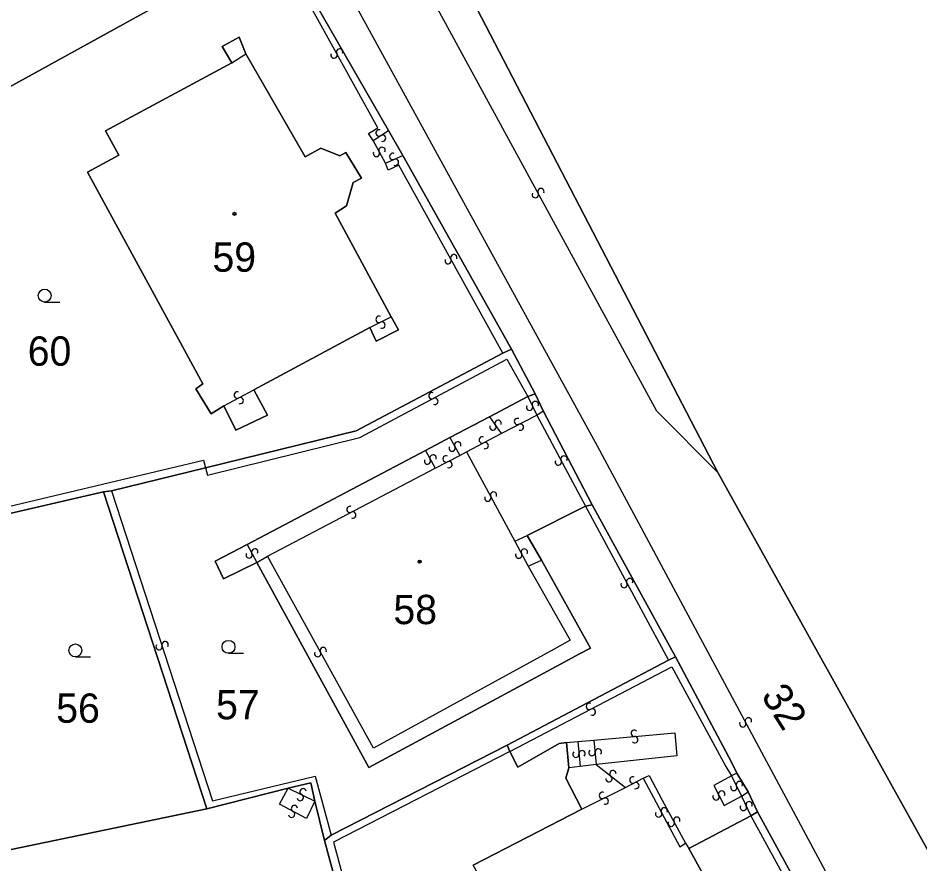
# Model space of a CAD drawing. Extents: x -600309 to -598967, y -1161267 to -1160292.
# Drawn here: x -599061.3 to -599009, y -1160829.7 to -1160780.7 of the extents above; entities that cross this region are included whole.
import ezdxf

# ---------------------------------------------------------------- set-up
doc = ezdxf.new("R2010")
doc.units = 0
for name, color, linetype in [('Level 1', 7, 'Continuous'), ('Level 13', 7, 'Continuous'), ('Level 3', 7, 'Continuous'), ('Level 4', 7, 'Continuous'), ('Level 5', 7, 'Continuous'), ('Level 57', 7, 'Continuous'), ('Level 60', 7, 'Continuous'), ('Vrstva 60', 7, 'Continuous')]:
    doc.layers.add(name, color=color, linetype=linetype)

msp = doc.modelspace()

# ---------------------------------------------------------------- linework, layer by layer
at = {"layer": 'Level 1'}
for points in [[(-598967.108, -1160884.839), (-598972.51, -1160879.73), (-598974.58, -1160878.03), (-598979.64, -1160873.91), (-598989.61, -1160863.67), (-598991.16, -1160861.71), (-599008.15, -1160829.7), (-599020.75, -1160807.03), (-599038.86, -1160772.13)], [(-599038.86, -1160772.13), (-599020.75, -1160807.03)], [(-599050.09, -1160778.17), (-599066.98, -1160787.5)], [(-599039.85, -1160787.18), (-599044.94, -1160778.29)], [(-599048.93, -1160783.27), (-599049.48, -1160782.31), (-599048.51, -1160781.78), (-599048.11, -1160782.75)], [(-599048.93, -1160783.27), (-599056.25, -1160787.2), (-599055.48, -1160788.62), (-599057.3, -1160789.6), (-599050.6, -1160801.88), (-599051.02, -1160802.17), (-599050.13, -1160803.62), (-599049.4, -1160803.16)], [(-599048.11, -1160782.75), (-599044.67, -1160788.71), (-599043.77, -1160788.21), (-599042.67, -1160788.66), (-599042.31, -1160788.46), (-599041.41, -1160789.96), (-599041.9, -1160790.21), (-599042.27, -1160791.56), (-599042.94, -1160791.99), (-599039.69, -1160797.99)], [(-599039.02, -1160788.63), (-599039.85, -1160787.18)], [(-599032.71, -1160799.87), (-599039.02, -1160788.63)], [(-599039.69, -1160797.99), (-599039.26, -1160798.75), (-599040.56, -1160799.41), (-599040.92, -1160798.62)], [(-599040.92, -1160798.62), (-599047.66, -1160802.23)], [(-599033.21, -1160800.1), (-599032.71, -1160799.87)], [(-599031.34, -1160802.47), (-599032.71, -1160799.87)], [(-599050.45, -1160806.76), (-599041.71, -1160804.6), (-599033.21, -1160800.1)], [(-599047.66, -1160802.23), (-599046.86, -1160803.69), (-599048.7, -1160804.57), (-599049.4, -1160803.16)], [(-599031.34, -1160802.47), (-599031.76, -1160802.62)], [(-599030.88, -1160803.45), (-599031.34, -1160802.47)], [(-599031.76, -1160802.62), (-599033.98, -1160803.79)], [(-599028.03, -1160808.9), (-599030.88, -1160803.45)], [(-599033.98, -1160803.79), (-599036.28, -1160805)], [(-599036.28, -1160805), (-599037.7, -1160805.75)], [(-599037.7, -1160805.75), (-599048.04, -1160811.2)], [(-599055.9, -1160808.08), (-599050.45, -1160806.76)], [(-599020.75, -1160807.03), (-599008.15, -1160829.7)], [(-599062.75, -1160809.62), (-599056.36, -1160808.14)], [(-599056.36, -1160808.14), (-599055.9, -1160808.08)], [(-599056.36, -1160808.14), (-599050.37, -1160826.54)], [(-599031.8, -1160810.67), (-599028.42, -1160808.97)], [(-599028.42, -1160808.97), (-599028.03, -1160808.9)], [(-599023.21, -1160817.72), (-599028.03, -1160808.9)], [(-599030.97, -1160812.1), (-599031.8, -1160810.67)], [(-599048.04, -1160811.2), (-599049.89, -1160812.16), (-599049.41, -1160813.2), (-599047.48, -1160812.24)], [(-599047.48, -1160812.24), (-599040.98, -1160824.14), (-599029.87, -1160818.14), (-599028.76, -1160817.55), (-599028.14, -1160817.21), (-599030.97, -1160812.1)], [(-599023.61, -1160817.9), (-599023.21, -1160817.72)], [(-599019.64, -1160824.46), (-599019.95, -1160823.82), (-599023.21, -1160817.72)], [(-599032.96, -1160822.84), (-599023.61, -1160817.9)], [(-599043.16, -1160828.06), (-599032.96, -1160822.84)], [(-599032.81, -1160823.21), (-599032.96, -1160822.84)], [(-599029.52, -1160822.68), (-599029.95, -1160822.75), (-599032.35, -1160824.12), (-599032.81, -1160823.21)], [(-599029.39, -1160824.15), (-599029.52, -1160822.68)], [(-599028.63, -1160826.55), (-599029.57, -1160824.76), (-599029.39, -1160824.15)], [(-599019, -1160825.54), (-599019.64, -1160824.46)], [(-599045.66, -1160825.34), (-599044.34, -1160825.02), (-599044.11, -1160826.08)], [(-599050.37, -1160826.54), (-599045.66, -1160825.34)], [(-599018.45, -1160826.7), (-599019, -1160825.54)], [(-599043.55, -1160828.36), (-599044.11, -1160826.08)], [(-599063.7, -1160829.3), (-599050.37, -1160826.54)], [(-599022.44, -1160828.84), (-599019.86, -1160833.47), (-599029.89, -1160838.75), (-599031.09, -1160838.89), (-599032.45, -1160838.52), (-599033.26, -1160837.58), (-599033.82, -1160836.06), (-599033.56, -1160834.59), (-599032.78, -1160833.61), (-599034.94, -1160829.79), (-599028.63, -1160826.55)], [(-599018.84, -1160826.94), (-599022.44, -1160828.84)], [(-599018.45, -1160826.7), (-599018.84, -1160826.94)], [(-599012.17, -1160838.2), (-599018.45, -1160826.7)], [(-599043.55, -1160828.36), (-599043.16, -1160828.06)], [(-599038.63, -1160846.55), (-599043.55, -1160828.36)]]:
    msp.add_lwpolyline(points, dxfattribs=at)
at = {"layer": 'Level 13'}
for centre, start, end in [((-599043.002, -1160782.808), 156.2751, 28.3731), ((-599042.678, -1160782.632), 336.0606, 208.6506), ((-599040.39, -1160787.325), 70.914, 303.012), ((-599040.189, -1160787.634), 250.6995, 123.2895), ((-599040.543, -1160788.517), 155.9832, 28.0812), ((-599040.218, -1160788.343), 335.7687, 208.3587), ((-599039.596, -1160788.692), 62.0752, 294.1732), ((-599039.444, -1160789.028), 241.8607, 114.4507), ((-599031.008, -1160790.733), 335.6989, 208.2889), ((-599031.333, -1160790.907), 155.9133, 28.0113), ((-599036.382, -1160794.738), 156.3246, 28.4226), ((-599036.059, -1160794.562), 336.1101, 208.7001), ((-599040.393, -1160798.145), 64.494, 296.592), ((-599040.227, -1160798.474), 244.2796, 116.8696), ((-599048.615, -1160802.527), 65.4965, 297.5945), ((-599037.325, -1160802.566), 65.4487, 297.5467), ((-599048.444, -1160802.853), 245.282, 117.872), ((-599037.154, -1160802.893), 245.2343, 117.8243), ((-599031.333, -1160803.081), 333.2916, 205.3896), ((-599031.666, -1160803.24), 153.0772, 25.6672), ((-599033.487, -1160804.177), 341.7321, 213.8301), ((-599032.364, -1160804.066), 64.9255, 297.0235), ((-599033.792, -1160804.383), 161.5177, 34.1077), ((-599032.196, -1160804.394), 244.7111, 117.3011), ((-599034.405, -1160805.136), 65.1782, 297.2762), ((-599036.151, -1160805.61), 156.5424, 29.1324), ((-599035.828, -1160805.431), 336.7569, 208.8549), ((-599034.235, -1160805.463), 244.9638, 117.5538), ((-599037.581, -1160806.358), 156.1183, 28.7083), ((-599037.258, -1160806.182), 336.3328, 208.4308), ((-599036.504, -1160806.236), 65.0486, 297.1466), ((-599029.667, -1160806.245), 335.479, 207.577), ((-599036.335, -1160806.563), 244.8342, 117.4242), ((-599029.993, -1160806.416), 155.2645, 27.8545), ((-599033.757, -1160808.334), 335.8121, 207.9101), ((-599034.082, -1160808.507), 155.5976, 28.1876), ((-599042.084, -1160809.166), 65.0341, 297.1321), ((-599041.915, -1160809.493), 244.8197, 117.4097), ((-599047.597, -1160811.634), 335.6735, 207.7715), ((-599031.967, -1160811.645), 335.4859, 207.5839), ((-599047.922, -1160811.807), 155.459, 28.049), ((-599032.293, -1160811.816), 155.2715, 27.8615), ((-599026.182, -1160813.527), 155.4667, 28.0567), ((-599025.857, -1160813.354), 335.6811, 207.7791), ((-599053.145, -1160817.126), 145.21, 17.8), ((-599052.794, -1160817.014), 325.4244, 197.5224), ((-599043.628, -1160817.352), 336.0421, 208.6321), ((-599043.952, -1160817.528), 156.2566, 28.3546), ((-599028.194, -1160820.586), 64.9526, 297.0506), ((-599028.026, -1160820.914), 244.7382, 117.3282), ((-599018.977, -1160821.434), 335.5647, 207.6627), ((-599019.303, -1160821.606), 155.3503, 27.9403), ((-599025.594, -1160822.156), 42.3688, 274.4668), ((-599025.565, -1160822.523), 222.1544, 94.7444), ((-599028.983, -1160823.366), 132.2465, 4.8365), ((-599028.616, -1160823.335), 312.461, 184.559), ((-599028.043, -1160823.266), 132.3527, 4.9427), ((-599027.676, -1160823.235), 312.5672, 184.6652), ((-599026.835, -1160824.496), 359.3348, 231.4328), ((-599027.064, -1160824.784), 179.1203, 51.7103), ((-599025.676, -1160824.857), 65.707, 297.805), ((-599025.503, -1160825.182), 245.4925, 118.0825), ((-599019.494, -1160825.129), 333.9378, 206.0358), ((-599044.799, -1160825.544), 11.852, 243.95), ((-599027.44, -1160825.754), 63.6654, 295.7634), ((-599020.525, -1160825.678), 334.3316, 206.4296), ((-599019.825, -1160825.292), 153.7233, 26.3133), ((-599044.96, -1160825.876), 191.6376, 64.2276), ((-599027.279, -1160826.085), 243.4509, 116.0409), ((-599020.854, -1160825.843), 154.1171, 26.7071), ((-599018.932, -1160826.294), 332.307, 204.405), ((-599045.294, -1160826.517), 9.4446, 242.0346), ((-599023.857, -1160826.654), 335.5274, 207.6253), ((-599019.267, -1160826.447), 152.0926, 24.6826), ((-599045.467, -1160826.842), 189.659, 61.757), ((-599024.183, -1160826.826), 155.3129, 27.9029), ((-599023.127, -1160827.194), 335.7418, 207.8398), ((-599023.452, -1160827.367), 155.5273, 28.1173)]:
    msp.add_arc(centre, 0.184, start, end, dxfattribs=at)
at = {"layer": 'Level 3'}
for points in [[(-599020.75, -1160807.03), (-599024.29, -1160803.47), (-599038.05, -1160778.17), (-599040.52, -1160772.93)], [(-599044.45, -1160775.03), (-599042.71, -1160778.18), (-599027.74, -1160805.48), (-599010.55, -1160837.55), (-598995.06, -1160866.56), (-598990.88, -1160872.86), (-598987.65, -1160876.63), (-598967.63, -1160897.91), (-598967.108, -1160898.408)], [(-599040.74, -1160787.77), (-599041.01, -1160787.36), (-599040.46, -1160787.04), (-599045.23, -1160778.4)], [(-599048.93, -1160783.27), (-599048.11, -1160782.75)], [(-599040.74, -1160787.77), (-599039.85, -1160787.18)], [(-599066.98, -1160787.5), (-599062.28, -1160809.1), (-599050.56, -1160806.31), (-599050.45, -1160806.76)], [(-599040.02, -1160789.09), (-599040.74, -1160787.77)], [(-599040.02, -1160789.09), (-599039.02, -1160788.63)], [(-599033.21, -1160800.1), (-599039.24, -1160789.2), (-599039.87, -1160789.48), (-599040.02, -1160789.09)], [(-599040.92, -1160798.62), (-599039.69, -1160797.99)], [(-599050.45, -1160806.76), (-599050.33, -1160807.18), (-599041.51, -1160805), (-599032.98, -1160800.45), (-599031.76, -1160802.62)], [(-599049.4, -1160803.16), (-599047.66, -1160802.23)], [(-599031.76, -1160802.62), (-599031.24, -1160803.69)], [(-599031.24, -1160803.69), (-599030.88, -1160803.45)], [(-599033.98, -1160803.79), (-599033.31, -1160804.77)], [(-599033.31, -1160804.77), (-599031.24, -1160803.69)], [(-599031.24, -1160803.69), (-599028.42, -1160808.97)], [(-599036.28, -1160805), (-599035.7, -1160806.03)], [(-599035.32, -1160805.83), (-599033.31, -1160804.77)], [(-599037.7, -1160805.75), (-599037.13, -1160806.78)], [(-599037.13, -1160806.78), (-599035.7, -1160806.03)], [(-599035.7, -1160806.03), (-599035.32, -1160805.83)], [(-599035.32, -1160805.83), (-599032.52, -1160811)], [(-599046.86, -1160811.88), (-599037.13, -1160806.78)], [(-599055.9, -1160808.08), (-599050.04, -1160826.06), (-599044.1, -1160824.63), (-599043.16, -1160828.06)], [(-599028.42, -1160808.97), (-599023.61, -1160817.9)], [(-599032.52, -1160811), (-599031.8, -1160810.67)], [(-599048.04, -1160811.2), (-599047.48, -1160812.24)], [(-599032.52, -1160811), (-599031.74, -1160812.46)], [(-599047.48, -1160812.24), (-599046.86, -1160811.88)], [(-599031.74, -1160812.46), (-599029.32, -1160816.74), (-599030.23, -1160817.27), (-599040.72, -1160823.01), (-599046.86, -1160811.88)], [(-599031.74, -1160812.46), (-599030.97, -1160812.1)], [(-599032.81, -1160823.21), (-599023.41, -1160818.3), (-599020.29, -1160824.07), (-599019.96, -1160824.62)], [(-599027.93, -1160822.54), (-599023.24, -1160822.13), (-599023.13, -1160823.45), (-599027.8, -1160823.97)], [(-599029.52, -1160822.68), (-599028.87, -1160822.62)], [(-599028.87, -1160822.62), (-599027.93, -1160822.54)], [(-599028.87, -1160822.62), (-599028.74, -1160824.08)], [(-599027.93, -1160822.54), (-599027.8, -1160823.97)], [(-599032.81, -1160823.21), (-599043.03, -1160828.47), (-599038.17, -1160846.39)], [(-599027.8, -1160823.97), (-599028.74, -1160824.08)], [(-599027.8, -1160823.97), (-599026.1, -1160825.3)], [(-599028.74, -1160824.08), (-599029.39, -1160824.15)], [(-599019.64, -1160824.46), (-599019.96, -1160824.62)], [(-599026.1, -1160825.3), (-599025.08, -1160824.75)], [(-599025.08, -1160824.75), (-599024.73, -1160824.59), (-599023.97, -1160826.03), (-599022.62, -1160828.53)], [(-599025.08, -1160824.75), (-599022.95, -1160828.73), (-599022.62, -1160828.53)], [(-599019.96, -1160824.62), (-599020.98, -1160825.18), (-599020.39, -1160826.34), (-599019.37, -1160825.8)], [(-599019.96, -1160824.62), (-599019.37, -1160825.8)], [(-599044.11, -1160826.08), (-599044.59, -1160827.1), (-599046.17, -1160826.27), (-599045.66, -1160825.34)], [(-599045.66, -1160825.34), (-599044.11, -1160826.08)], [(-599028.63, -1160826.55), (-599026.1, -1160825.3)], [(-599019.37, -1160825.8), (-599019, -1160825.54)], [(-599019.37, -1160825.8), (-599018.84, -1160826.94)], [(-599018.84, -1160826.94), (-599012.62, -1160838.33)], [(-599022.62, -1160828.53), (-599022.44, -1160828.84)]]:
    msp.add_lwpolyline(points, dxfattribs=at)
at = {"layer": 'Level 5'}
for p, q in [((-599059.78, -1160797.14), (-599058.905, -1160797.14)), ((-599058, -1160817.72), (-599057.125, -1160817.72)), ((-599049.12, -1160817.51), (-599048.245, -1160817.51))]:
    msp.add_line(p, q, dxfattribs=at)
for centre, radius in [((-599048.77, -1160792.02), 0.09), ((-599048.77, -1160792.02), 0.0521), ((-599059.78, -1160796.765), 0.375), ((-599038.04, -1160812.2), 0.09), ((-599038.04, -1160812.2), 0.0521), ((-599058, -1160817.345), 0.375), ((-599049.12, -1160817.135), 0.375)]:
    msp.add_circle(centre, radius, dxfattribs=at)
at = {"layer": 'Level 60'}
for points in [[(-599074.8, -1160633.37), (-599072.29, -1160646.3), (-599071.63, -1160649.97), (-599069.19, -1160662.47), (-599062.42, -1160697.34), (-599058.05, -1160720.03), (-599057.39, -1160723.33), (-599052.68, -1160747.38), (-599049.58, -1160762.75), (-599048.05, -1160769.81), (-599046.8, -1160774.69), (-599046.22, -1160775.87), (-599050.09, -1160778.17), (-599066.98, -1160787.5), (-599067.47, -1160787.83), (-599068.04, -1160784.69), (-599078.87, -1160791.24), (-599085.73, -1160791.88), (-599086.32, -1160791.93), (-599104.44, -1160657.19), (-599104.72, -1160655.07), (-599117.85, -1160556.94)], [(-599034.94, -1160829.79), (-599028.63, -1160826.55), (-599029.57, -1160824.76), (-599029.39, -1160824.15), (-599029.52, -1160822.68), (-599029.95, -1160822.75), (-599032.35, -1160824.12), (-599032.81, -1160823.21), (-599032.96, -1160822.84), (-599023.61, -1160817.9), (-599023.21, -1160817.72), (-599019.95, -1160823.82), (-599019.64, -1160824.46), (-599019, -1160825.54), (-599018.45, -1160826.7), (-599018.84, -1160826.94), (-599022.44, -1160828.84), (-599019.86, -1160833.47)], [(-599038.63, -1160846.55), (-599043.55, -1160828.36), (-599043.16, -1160828.06), (-599032.96, -1160822.84), (-599032.81, -1160823.21), (-599032.35, -1160824.12), (-599029.95, -1160822.75), (-599029.52, -1160822.68), (-599029.39, -1160824.15), (-599029.57, -1160824.76), (-599028.63, -1160826.55), (-599034.94, -1160829.79)], [(-599019.86, -1160833.47), (-599022.44, -1160828.84), (-599018.84, -1160826.94), (-599018.45, -1160826.7), (-599012.17, -1160838.2)]]:
    msp.add_lwpolyline(points, dxfattribs=at)
for points in [[(-599050.09, -1160778.17), (-599046.22, -1160775.87), (-599044.94, -1160778.29), (-599039.85, -1160787.18), (-599039.02, -1160788.63), (-599032.71, -1160799.87), (-599033.21, -1160800.1), (-599041.71, -1160804.6), (-599050.45, -1160806.76), (-599055.9, -1160808.08), (-599056.36, -1160808.14), (-599062.75, -1160809.62), (-599065.44, -1160796.64), (-599065.56, -1160796.09), (-599067.47, -1160787.83), (-599066.98, -1160787.5)], [(-599056.25, -1160787.2), (-599048.93, -1160783.27), (-599049.48, -1160782.31), (-599048.51, -1160781.78), (-599048.11, -1160782.75), (-599044.67, -1160788.71), (-599043.77, -1160788.21), (-599042.67, -1160788.66), (-599042.31, -1160788.46), (-599041.41, -1160789.96), (-599041.9, -1160790.21), (-599042.27, -1160791.56), (-599042.94, -1160791.99), (-599039.69, -1160797.99), (-599039.26, -1160798.75), (-599040.56, -1160799.41), (-599040.92, -1160798.62), (-599047.66, -1160802.23), (-599046.86, -1160803.69), (-599048.7, -1160804.57), (-599049.4, -1160803.16), (-599050.13, -1160803.62), (-599051.02, -1160802.17), (-599050.6, -1160801.88), (-599057.3, -1160789.6), (-599055.48, -1160788.62)], [(-599048.93, -1160783.27), (-599056.25, -1160787.2), (-599055.48, -1160788.62), (-599057.3, -1160789.6), (-599050.6, -1160801.88), (-599051.02, -1160802.17), (-599050.13, -1160803.62), (-599049.4, -1160803.16), (-599048.7, -1160804.57), (-599046.86, -1160803.69), (-599047.66, -1160802.23), (-599040.92, -1160798.62), (-599040.56, -1160799.41), (-599039.26, -1160798.75), (-599039.69, -1160797.99), (-599042.94, -1160791.99), (-599042.27, -1160791.56), (-599041.9, -1160790.21), (-599041.41, -1160789.96), (-599042.31, -1160788.46), (-599042.67, -1160788.66), (-599043.77, -1160788.21), (-599044.67, -1160788.71), (-599048.11, -1160782.75), (-599048.51, -1160781.78), (-599049.48, -1160782.31)], [(-599028.03, -1160808.9), (-599023.21, -1160817.72), (-599023.61, -1160817.9), (-599032.96, -1160822.84), (-599043.16, -1160828.06), (-599043.55, -1160828.36), (-599044.11, -1160826.08), (-599044.34, -1160825.02), (-599045.66, -1160825.34), (-599050.37, -1160826.54), (-599056.36, -1160808.14), (-599055.9, -1160808.08), (-599050.45, -1160806.76), (-599041.71, -1160804.6), (-599033.21, -1160800.1), (-599032.71, -1160799.87), (-599031.34, -1160802.47), (-599031.76, -1160802.62), (-599033.98, -1160803.79), (-599036.28, -1160805), (-599037.7, -1160805.75), (-599048.04, -1160811.2), (-599049.89, -1160812.16), (-599049.41, -1160813.2), (-599047.48, -1160812.24), (-599040.98, -1160824.14), (-599029.87, -1160818.14), (-599028.76, -1160817.55), (-599028.14, -1160817.21), (-599030.97, -1160812.1), (-599031.8, -1160810.67), (-599028.42, -1160808.97)], [(-599030.88, -1160803.45), (-599028.03, -1160808.9), (-599028.42, -1160808.97), (-599031.8, -1160810.67), (-599030.97, -1160812.1), (-599028.14, -1160817.21), (-599028.76, -1160817.55), (-599029.87, -1160818.14), (-599040.98, -1160824.14), (-599047.48, -1160812.24), (-599049.41, -1160813.2), (-599049.89, -1160812.16), (-599048.04, -1160811.2), (-599037.7, -1160805.75), (-599036.28, -1160805), (-599033.98, -1160803.79), (-599031.76, -1160802.62), (-599031.34, -1160802.47)], [(-599050.37, -1160826.54), (-599063.7, -1160829.3), (-599064.19, -1160829.27), (-599064.53, -1160821.61), (-599064.36, -1160821.58), (-599062.63, -1160821.32), (-599062.9, -1160819.83), (-599063.43, -1160816.76), (-599065.98, -1160816.96), (-599066.49, -1160812.26), (-599066.65, -1160810.49), (-599062.75, -1160809.62), (-599056.36, -1160808.14)], [(-599056.09, -1160847.43), (-599062.58, -1160847.78), (-599062.95, -1160841.27), (-599063.32, -1160841.25), (-599063.63, -1160837.22), (-599063.2, -1160837.18), (-599063.7, -1160829.3), (-599050.37, -1160826.54), (-599045.66, -1160825.34), (-599044.34, -1160825.02), (-599044.11, -1160826.08), (-599043.55, -1160828.36), (-599038.63, -1160846.55)]]:
    msp.add_lwpolyline(points, close=True, dxfattribs=at)
at = {"layer": 'Vrstva 60'}
for points in [[(-599038.86, -1160772.13), (-599020.75, -1160807.03), (-599008.15, -1160829.7), (-598991.16, -1160861.71), (-598989.61, -1160863.67), (-598979.64, -1160873.91), (-598974.58, -1160878.03), (-598972.51, -1160879.73), (-598967.108, -1160884.839), (-598967.108, -1160872.375), (-598969.4, -1160869.7), (-598971.3, -1160866.53), (-598974.52, -1160855), (-598967.76, -1160834.36), (-598967.108, -1160834.936), (-598967.108, -1160799.774), (-598974.62, -1160792.64), (-598983.72, -1160784.03), (-598987.65, -1160780.53)], [(-598989.61, -1160863.67), (-598991.16, -1160861.71), (-599008.15, -1160829.7), (-599020.75, -1160807.03), (-599038.86, -1160772.13)], [(-599044.94, -1160778.29), (-599039.85, -1160787.18), (-599039.02, -1160788.63), (-599032.71, -1160799.87), (-599031.34, -1160802.47), (-599030.88, -1160803.45), (-599028.03, -1160808.9), (-599023.21, -1160817.72), (-599019.95, -1160823.82), (-599019.64, -1160824.46), (-599019, -1160825.54), (-599018.45, -1160826.7), (-599012.17, -1160838.2), (-599010.36, -1160841.52), (-599009.91, -1160842.46), (-599003.95, -1160853.72), (-598997.36, -1160865.86)]]:
    msp.add_lwpolyline(points, dxfattribs=at)

# ---------------------------------------------------------------- texts
at = {"layer": 'Level 4'}
for s, p in [('59', (-599050.05, -1160795.38)), ('60', (-599060.76, -1160800.83)), ('58', (-599039.56, -1160815.82)), ('56', (-599059.11, -1160821.54)), ('57', (-599049.84, -1160821.34))]:
    msp.add_text(s, height=1.7, dxfattribs=at).set_placement(p)
at = {"layer": 'Level 57'}
msp.add_text('32', height=1.7, rotation=302.4, dxfattribs=at).set_placement((-599018.28, -1160819.97))

doc.saveas('drawing.dxf')
